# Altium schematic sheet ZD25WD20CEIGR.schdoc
size 127 x 101 mm
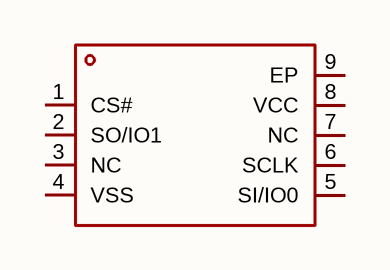
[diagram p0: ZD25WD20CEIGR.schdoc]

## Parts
U?  zd25wd20ceigr  [USON-8_L3.0-W2.0-P0.50-BL-EP_ZD25XX]  (value not drawn)

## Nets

Not connected (* = marked no-connect by the designer): U? 1(CS#) 2(SO/IO1) 3(NC) 4(VSS) 5(SI/IO0) 6(SCLK) 7(NC) 8(VCC) 9(EP)

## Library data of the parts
U? = zd25wd20ceigr: 接口类型:SPI;存储容量:2Mbit;时钟频率(fc):104MHz;; Manufacturer: Zetta(澜智); AddInBom: yes; ModelId: 12a239e5c7384371915ecb51201bf581; ModelName: USON-8_L3.0-W2.0-H0.6-P0.50; ModelTransform: 118.8974,78.74,0,90,0,0,0,0,0; Interface: SPI; Memory Size: 2Mbit; Clock Frequency: 104MHz; Voltage - Supply: 1.65V~3.6V; Standby Supply Current: 0.5uA; Program / Erase Cycles: 100000次; Page Programming Time (Tpp): 2ms; Data Retention - TDR (Year): 20年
